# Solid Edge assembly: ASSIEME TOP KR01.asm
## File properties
Subject: ASSIEME BASE KR01
Author: f_grande
Template: Normal.asm
Last saved by: f_grande
Revision: 140
Application: Solid Edge
Tipo di contenuto documento: 1
Document Number: KR0118
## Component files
MANICOTTO_20.par
ALBERO_12X250.par
SUPP 2 ASSE Z.par
SUPPORTO CUSC 6200.par
TRAVERSA ALLUMINIO_702.par
BASE ASSE Z.par
IRRIGIDIMENTO SUP.par
MANICOTTO_12.par
VITE RICIRCOLO_810.par
LAT ASSE Z.par
GUIDA_20.par
6200.asm
CHIOCCIOLA.par
TCE M5x15.par
7201_BEGAP.asm
Rosetta-D8.par
TOP ASSE Z.par
BOCCOLA M12.par
TCE M8x35.par
supporto led.asm
Asm2.asm
KRESS1050.par
LATERALE DX.par
ALLUMINIO_702.par
ASSIEME MOTORE.asm
TSPE M4x20.par
MANICOTTO_25.par
SUPPORTO_12.par
SUPP 1 ASSE Z.par
VITE RICIRCOLO_310.par
LATERALE SX.par
SUPPORTO KRESS1050.par
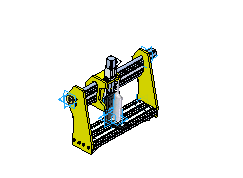
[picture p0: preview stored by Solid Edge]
